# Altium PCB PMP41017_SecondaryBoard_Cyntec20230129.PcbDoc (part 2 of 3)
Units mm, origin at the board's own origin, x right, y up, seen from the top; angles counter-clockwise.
Board outline 56.93 x 50 mm, 6 copper layers (Top Layer, Layer 1, Layer 3, Layer 4, Layer 2, Bottom Layer), stack 1.219 mm thick; 147 components, 63 nets, 876 pads, 1174 vias.
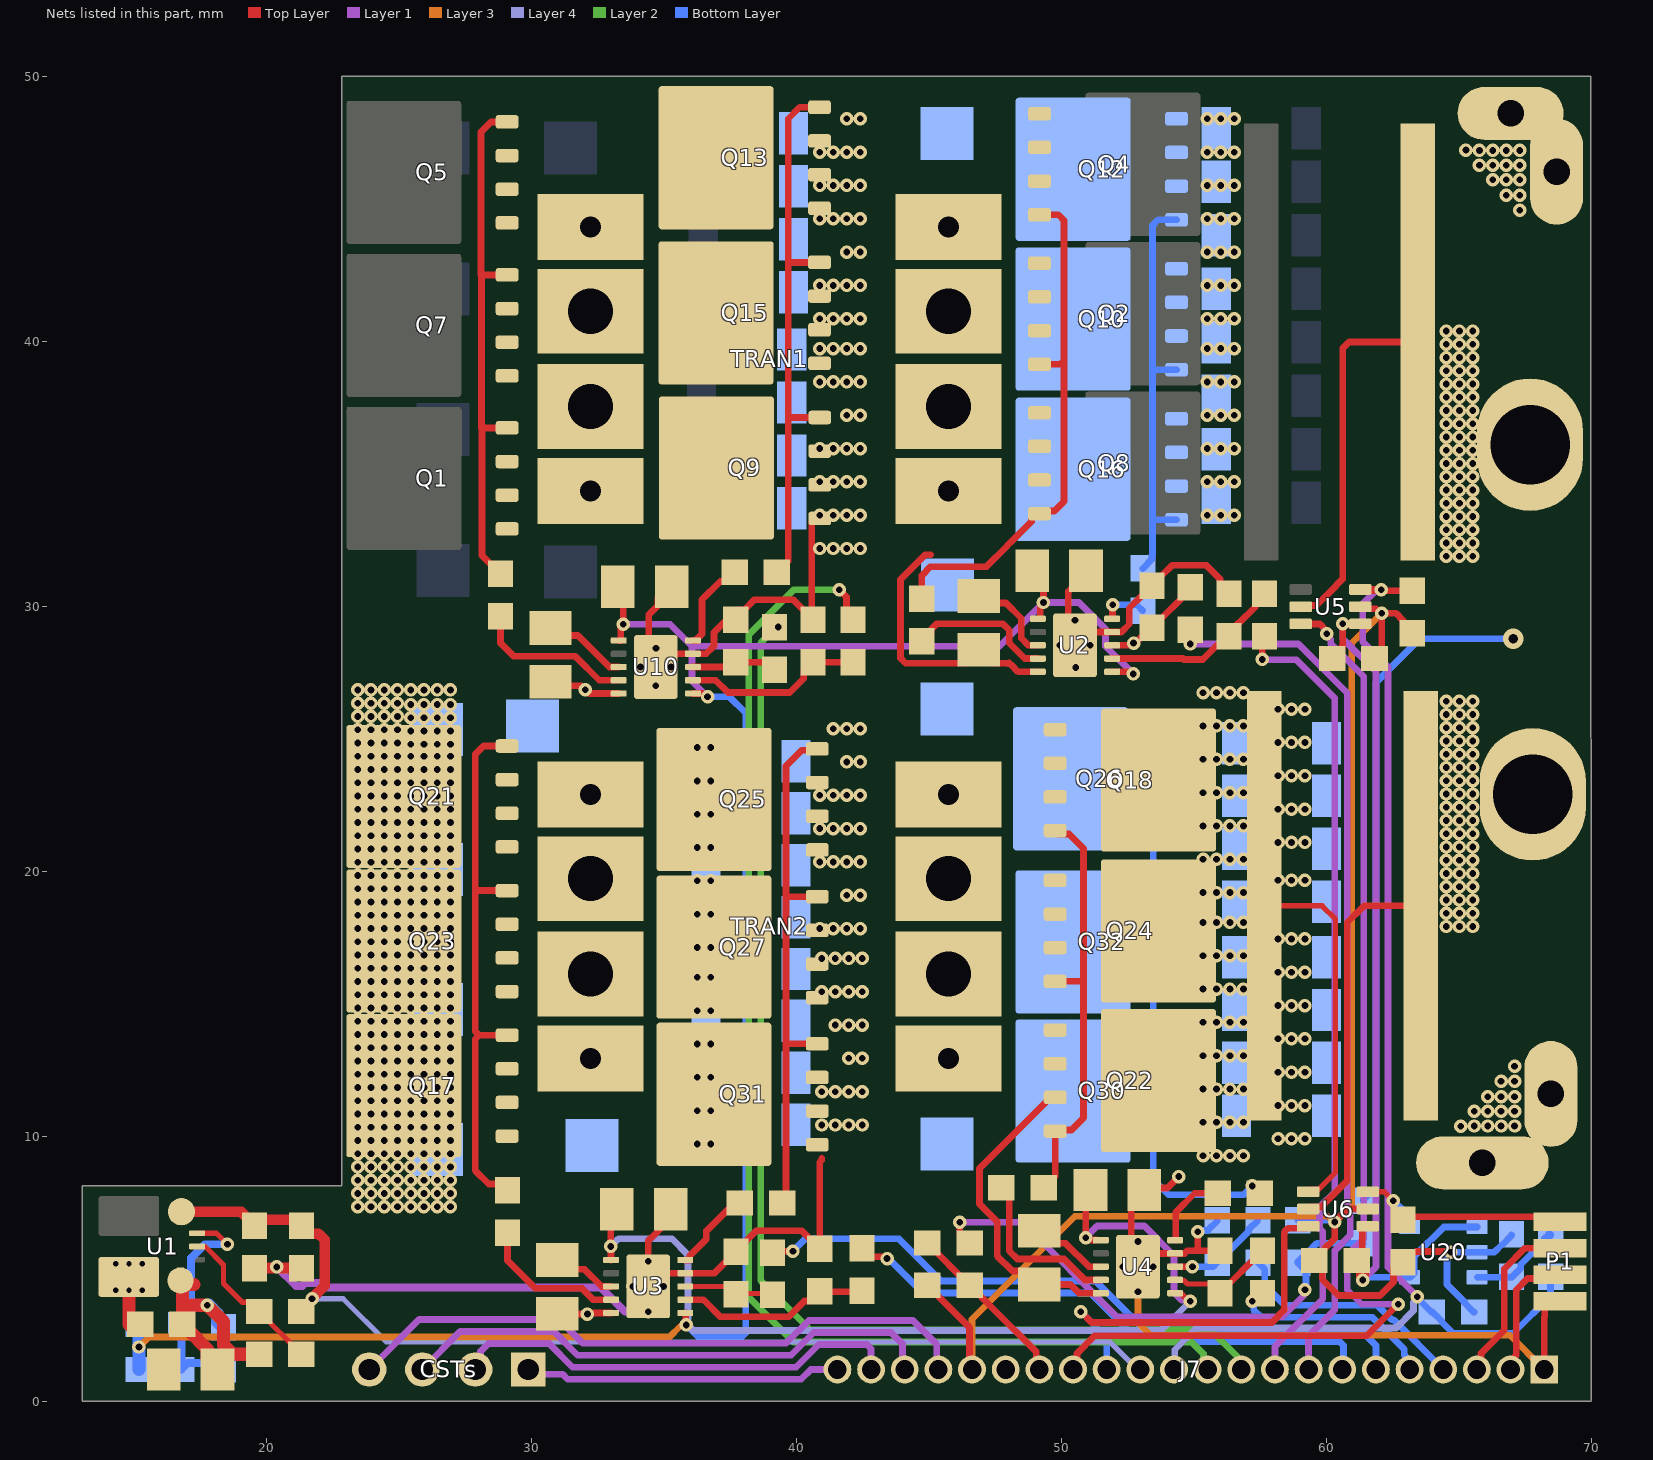
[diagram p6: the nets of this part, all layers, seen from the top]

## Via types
v1: diameter 0.508, hole 0.254, Top Layer to Bottom Layer, tented both sides, 996 vias
v2: diameter 0.508, hole 0.254, Layer 2 to Bottom Layer, tented both sides, 151 vias
v3: diameter 0.508, hole 0.254, Top Layer to Bottom Layer, 14 vias
v4: diameter 0.5, hole 0.2, Top Layer to Bottom Layer, 12 vias
v5: diameter 0.762, hole 0.356, Top Layer to Bottom Layer, tented both sides, 1 vias

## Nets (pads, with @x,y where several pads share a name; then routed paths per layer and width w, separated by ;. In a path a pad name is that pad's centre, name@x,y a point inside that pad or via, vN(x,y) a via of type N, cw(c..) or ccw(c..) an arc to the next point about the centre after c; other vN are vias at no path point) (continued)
12Vo_B: C25.1 C26.1 C27.1 C28.1 C29.1 C30.1 C31.1 C32.1 C33.1 C34.1 C35.1 C36.1 C37.1 C38.1 C39.1 C40.1 MP7.1 MP8.1 MP9.1 MP10.1 MP11.1 MP12.1 Q17.5 Q17.6 Q17.7 Q17.8 Q17.9@25.196,11.911 Q18.5 Q18.6 Q18.7 Q18.8 Q18.9@53.676,23.442 Q21.5 Q21.6 Q21.7 Q21.8 Q21.9@25.196,22.823 Q22.5 Q22.6 Q22.7 Q22.8 Q22.9@53.676,12.102 Q23.5 Q23.6 Q23.7 Q23.8 Q23.9@25.196,17.367 Q24.5 Q24.6 Q24.7 Q24.8 Q24.9@53.676,17.752 R56.2 R94.2 R97.2 R105.2 R117.2 U6.4 | length 13.6
  Top Layer w0.2: R117.2@57.675,18.696 59.854,18.696 60.356,18.194 60.356,8.635 59.727,8.005 U6.4@59.426,8.005
  other v1: 23.456,7.343 23.956,7.343 24.456,7.343 24.956,7.343 25.456,7.343 25.956,7.343 26.456,7.343 26.956,7.343 23.456,7.843 23.956,7.843 24.456,7.843 24.956,7.843 25.456,7.843 25.956,7.843 26.456,7.843 26.956,7.843 23.456,8.343 23.956,8.343 24.456,8.343 24.956,8.343 25.456,8.343 25.956,8.343 26.456,8.343 26.956,8.343 23.456,8.843 23.956,8.843 24.456,8.843 24.956,8.843 25.456,8.843 25.956,8.843 26.456,8.843 26.956,8.843 23.456,9.343 23.956,9.343 24.456,9.343 24.956,9.343 25.456,9.343 25.956,9.343 26.456,9.343 26.956,9.343 23.456,9.843 23.956,9.843 24.456,9.843 24.956,9.843 25.456,9.843 25.956,9.843 26.456,9.843 26.956,9.843 58.187,9.904 58.695,9.904 59.203,9.904 23.456,10.343 23.956,10.343 24.456,10.343 24.956,10.343 25.456,10.343 25.956,10.343 26.456,10.343 26.956,10.343 23.456,10.843 23.956,10.843 24.456,10.843 24.956,10.843 25.456,10.843 25.956,10.843 26.456,10.843 26.956,10.843 58.187,11.161 58.695,11.161 59.203,11.161 23.456,11.343 23.956,11.343 24.456,11.343 24.956,11.343 25.456,11.343 25.956,11.343 26.456,11.343 26.956,11.343 23.456,11.843 23.956,11.843 24.456,11.843 24.956,11.843 25.456,11.843 25.956,11.843 26.456,11.843 26.956,11.843 23.456,12.343 23.956,12.343 24.456,12.343 24.956,12.343 25.456,12.343 25.956,12.343 26.456,12.343 26.956,12.343 58.187,12.418 58.695,12.418 59.203,12.418 23.456,12.843 23.956,12.843 24.456,12.843 24.956,12.843 25.456,12.843 25.956,12.843 26.456,12.843 26.956,12.843 23.456,13.343 23.956,13.343 24.456,13.343 24.956,13.343 25.456,13.343 25.956,13.343 26.456,13.343 26.956,13.343 58.187,13.676 58.695,13.676 59.203,13.676 23.456,13.843 23.956,13.843 24.456,13.843 24.956,13.843 25.456,13.843 25.956,13.843 26.456,13.843 26.956,13.843 23.456,14.343 23.956,14.343 24.456,14.343 24.956,14.343 25.456,14.343 25.956,14.343 26.456,14.343 26.956,14.343 23.456,14.843 23.956,14.843 24.456,14.843 24.956,14.843 25.456,14.843 25.956,14.843 26.456,14.843 26.956,14.843 58.187,14.933 58.695,14.933 59.203,14.933 23.456,15.343 23.956,15.343 24.456,15.343 24.956,15.343 25.456,15.343 25.956,15.343 26.456,15.343 26.956,15.343 23.456,15.843 23.956,15.843 24.456,15.843 24.956,15.843 25.456,15.843 25.956,15.843 26.456,15.843 26.956,15.843 58.187,16.191 58.695,16.191 59.203,16.191 23.456,16.343 23.956,16.343 24.456,16.343 24.956,16.343 25.456,16.343 25.956,16.343 26.456,16.343 26.956,16.343 23.456,16.843 23.956,16.843 24.456,16.843 24.956,16.843 25.456,16.843 25.956,16.843 26.456,16.843 26.956,16.843 23.456,17.343 23.956,17.343 24.456,17.343 24.956,17.343 25.456,17.343 25.956,17.343 26.456,17.343 26.956,17.343 58.187,17.448 58.695,17.448 59.203,17.448 23.456,17.843 23.956,17.843 24.456,17.843 24.956,17.843 25.456,17.843 25.956,17.843 26.456,17.843 26.956,17.843 23.456,18.343 23.956,18.343 24.456,18.343 24.956,18.343 25.456,18.343 25.956,18.343 26.456,18.343 26.956,18.343 23.456,18.843 23.956,18.843 24.456,18.843 24.956,18.843 25.456,18.843 25.956,18.843 26.456,18.843 26.956,18.843 23.456,19.343 23.956,19.343 24.456,19.343 24.956,19.343 25.456,19.343 25.956,19.343 26.456,19.343 26.956,19.343 58.187,19.657 58.695,19.657 59.203,19.657 23.456,19.843 23.956,19.843 24.456,19.843 24.956,19.843 25.456,19.843 25.956,19.843 26.456,19.843 26.956,19.843 23.456,20.343 23.956,20.343 24.456,20.343 24.956,20.343 25.456,20.343 25.956,20.343 26.456,20.343 26.956,20.343 23.456,20.843 23.956,20.843 24.456,20.843 24.956,20.843 25.456,20.843 25.956,20.843 26.456,20.843 26.956,20.843 58.187,21.089 58.695,21.089 59.203,21.089 23.456,21.343 23.956,21.343 24.456,21.343 24.956,21.343 25.456,21.343 25.956,21.343 26.456,21.343 26.956,21.343 23.456,21.843 23.956,21.843 24.456,21.843 24.956,21.843 25.456,21.843 25.956,21.843 26.456,21.843 26.956,21.843 23.456,22.343 23.956,22.343 24.456,22.343 24.956,22.343 25.456,22.343 25.956,22.343 26.456,22.343 26.956,22.343 58.187,22.346 58.695,22.346 59.203,22.346 23.456,22.843 23.956,22.843 24.456,22.843 24.956,22.843 25.456,22.843 25.956,22.843 26.456,22.843 26.956,22.843 23.456,23.343 23.956,23.343 24.456,23.343 24.956,23.343 25.456,23.343 25.956,23.343 26.456,23.343 26.956,23.343 58.187,23.603 58.695,23.603 59.203,23.603 23.456,23.843 23.956,23.843 24.456,23.843 24.956,23.843 25.456,23.843 25.956,23.843 26.456,23.843 26.956,23.843 23.456,24.343 23.956,24.343 24.456,24.343 24.956,24.343 25.456,24.343 25.956,24.343 26.456,24.343 26.956,24.343 25.456,24.79 25.956,24.79 26.456,24.79 26.956,24.79 23.456,24.843 23.956,24.843 24.456,24.843 24.956,24.843 58.187,24.861 58.695,24.861 59.203,24.861 25.456,25.29 25.956,25.29 26.456,25.29 26.956,25.29 23.456,25.343 23.956,25.343 24.456,25.343 24.956,25.343 25.456,25.79 25.956,25.79 26.456,25.79 26.956,25.79 23.456,25.843 23.956,25.843 24.456,25.843 24.956,25.843 58.187,26.118 58.695,26.118 59.203,26.118 25.456,26.29 25.956,26.29 26.456,26.29 26.956,26.29 23.456,26.343 23.956,26.343 24.456,26.343 24.956,26.343 23.456,26.843 23.956,26.843 24.456,26.843 24.956,26.843 25.456,26.843 25.956,26.843 26.456,26.843 26.956,26.843
  other v2: 36.272,9.711 36.78,9.711 36.272,10.969 36.78,10.969 36.272,12.226 36.78,12.226 36.272,13.484 36.78,13.484 36.272,14.741 36.78,14.741 36.272,15.998 36.78,15.998 36.272,17.124 36.78,17.124 36.272,18.381 36.78,18.381 36.272,19.639 36.78,19.639 36.272,20.896 36.78,20.896 36.272,22.154 36.78,22.154 36.272,23.411 36.78,23.411 36.272,24.668 36.78,24.668
12Vout: pad.4@67.7,36.1 pad.5 R26.1 R29.1 R56.1 R89.1 R92.1 R94.1 R96.1 R97.1 R105.1 R108.1 R117.1 U5.5 U6.5 | length 54
  Top Layer w0.254: U5.5@59.043,29.984 59.084,30.025 59.629,30.025 60.128,30.524 60.128,30.527 60.627,31.026 60.627,39.727 60.873,39.973 R29.1@63.453,39.973 ; U6.5@59.399,7.328 59.804,7.328 59.854,7.378 59.858,7.378 60.078,7.599 60.078,7.602 60.796,8.32 60.796,18.057 61.436,18.696 R117.1@63.575,18.696
  Bottom Layer w0.254: R96.1@61.403,7.567 61.403,7.592 61.88,8.07 61.88,27.129 63.523,28.771 v5(67.061,28.771) ; pad.5@67.8,22.777 pad.5@67.8,22.9
  other v1: 64.532,17.916 65.032,17.916 65.532,17.916 64.532,18.416 65.032,18.416 65.532,18.416 64.532,18.916 65.032,18.916 65.532,18.916 64.532,19.416 65.032,19.416 65.532,19.416 64.532,19.916 65.032,19.916 65.532,19.916 64.532,20.416 65.032,20.416 65.532,20.416 64.532,20.916 65.032,20.916 65.532,20.916 64.532,21.416 65.032,21.416 65.532,21.416 64.532,21.916 65.032,21.916 65.532,21.916 64.532,22.416 65.032,22.416 65.532,22.416 64.532,22.916 65.032,22.916 65.532,22.916 64.532,23.416 65.032,23.416 65.532,23.416 64.532,23.916 65.032,23.916 65.532,23.916 64.532,24.416 65.032,24.416 65.532,24.416 64.532,24.916 65.032,24.916 65.532,24.916 64.532,25.416 65.032,25.416 65.532,25.416 64.532,25.916 65.032,25.916 65.532,25.916 64.532,26.416 65.032,26.416 65.532,26.416 64.532,31.886 65.032,31.886 65.532,31.886 64.532,32.386 65.032,32.386 65.532,32.386 64.532,32.886 65.032,32.886 65.532,32.886 64.532,33.386 65.032,33.386 65.532,33.386 64.532,33.886 65.032,33.886 65.532,33.886 64.532,34.386 65.032,34.386 65.532,34.386 64.532,34.886 65.032,34.886 65.532,34.886 64.532,35.386 65.032,35.386 65.532,35.386 64.532,35.886 65.032,35.886 65.532,35.886 64.532,36.386 65.032,36.386 65.532,36.386 64.532,36.886 65.032,36.886 65.532,36.886 64.532,37.386 65.032,37.386 65.532,37.386 64.532,37.886 65.032,37.886 65.532,37.886 64.532,38.386 65.032,38.386 65.532,38.386 64.532,38.886 65.032,38.886 65.532,38.886 64.532,39.386 65.032,39.386 65.532,39.386 64.532,39.886 65.032,39.886 65.532,39.886 64.532,40.386 65.032,40.386 65.532,40.386
12Vs: C5.1 C6.1 J7.13 R1.1 U1.1 | length 42.6
  Top Layer w0.2: C5.1@19.183,6.228 19.558,6.603 C5.1@19.558,6.628 ; C5.1@19.454,6.757 19.583,6.628 C5.1@19.59,6.635 ; R1.1@21.336,3.384 21.736,3.784 v1(21.736,3.868) ; C6.1@21.336,6.603 21.431,6.508 21.711,6.228 C6.1@21.736,6.228
  Top Layer w0.4: U1.1@16.806,7.154 19.057,7.154 C5.1@19.454,6.757 ; C5.1@19.59,6.635 19.81,6.856 21.109,6.856 C6.1@21.336,6.628 21.336,6.603 21.611,6.328 21.977,6.328 22.211,6.094 22.211,4.362 21.736,3.887 v1(21.736,3.868)
  Layer 4 w0.2: v1(21.736,3.868) 22.911,3.868 24.538,2.24 51.847,2.24 52.887,1.2 J7.13@52.99,1.2
LV_SW1A: C19.2 Q1.1 Q1.2 Q1.3 Q5.1 Q5.2 Q5.3 Q7.1 Q7.2 Q7.3 Q9.5 Q9.6 Q9.7 Q9.8 Q9.9@36.993,35.219 Q13.5 Q13.6 Q13.7 Q13.8 Q13.9@36.983,46.925 Q15.5 Q15.6 Q15.7 Q15.8 Q15.9@36.983,41.072 TRAN1.1 TRAN1.1ab TRAN1.1cd TRAN1.1e U10.5 | length 2.8
  Top Layer w0.254: C19.2@30.712,26.911 C19.2@30.76,26.959 ; C19.2@30.734,27.15 30.884,27 31.895,27 32.186,26.709 U10.5@33.306,26.709
  other v1: 32.041,26.854
LV_SW1B: C20.2 MP13.1 MP15.1 Q2.1 Q2.2 Q2.3 Q4.1 Q4.2 Q4.3 Q8.1 Q8.2 Q8.3 Q10.5 Q10.6 Q10.7 Q10.8 Q10.9@50.455,40.834 Q12.5 Q12.6 Q12.7 Q12.8 Q12.9@50.456,46.49 Q16.5 Q16.6 Q16.7 Q16.8 Q16.9@50.455,35.171 TRAN1.2 TRAN1.2ab TRAN1.2cd TRAN1.2e U2.5 | length 10.3
  Top Layer w0.254: 45.072,31.948 44.884,31.948 43.943,31.007 43.943,28.041 44.135,27.85 46.383,27.85 C20.2@46.889,28.355 47.397,27.847 47.988,27.847 48.008,27.827 ; 48.044,27.862 48.044,27.86 48.126,27.778 48.128,27.778 48.379,27.527 U2.5@49.125,27.527
LV_SW2A: C43.2 Q17.1 Q17.2 Q17.3 Q21.1 Q21.2 Q21.3 Q23.1 Q23.2 Q23.3 Q25.5 Q25.6 Q25.7 Q25.8 Q25.9@36.901,22.712 Q27.5 Q27.6 Q27.7 Q27.8 Q27.9@36.901,17.136 Q31.5 Q31.6 Q31.7 Q31.8 Q31.9@36.901,11.586 TRAN2.1 TRAN2.1ab TRAN2.1cd TRAN2.1e U3.5 | length 2
  Top Layer w0.25: C43.2@30.988,3.302 30.997,3.293 v1(32.128,3.293) ; v1@32.131,3.302 32.163,3.334 U3.5@33.02,3.334
LV_SW2B: C44.2 MP14.1 MP16.1 Q18.1 Q18.2 Q18.3 Q22.1 Q22.2 Q22.3 Q24.1 Q24.2 Q24.3 Q26.5 Q26.6 Q26.7 Q26.8 Q26.9@50.36,23.491 Q30.5 Q30.6 Q30.7 Q30.8 Q30.9@50.455,11.712 Q32.5 Q32.6 Q32.7 Q32.8 Q32.9@50.455,17.335 TRAN2.2 TRAN2.2ab TRAN2.2cd TRAN2.2e U4.5 | length 12
  Top Layer w0.254: Q22.3@49.776,11.467 49.601,11.467 46.92,8.786 46.92,7.448 47.59,6.778 47.59,5.49 48.165,4.915 48.672,4.915 C44.2@49.18,4.407 50.352,4.407 50.679,4.08 U4.5@51.502,4.08
NetC19_1: C19.1 U10.3 | length 2.8
  Top Layer w0.254: C19.1@31.021,28.896 31.766,28.896 32.953,27.709 U10.3@33.306,27.709
NetC20_1: C20.1 U2.3 | length 3.4
  Top Layer w0.254: C20.1@46.889,30.387 47.151,30.125 47.921,30.125 48.498,29.548 48.498,28.801 48.772,28.527 U2.3@49.125,28.527
NetC21_2: C21.2 R47.2 U10.8 | length 3.1
  Top Layer w0.254: U10.8@36.106,27.709 C21.2@37.722,27.709 ; C21.2@37.722,27.89 R47.2@39.186,27.89
NetC22_2: C22.2 R42.2 U10.7 | length 6.9
  Top Layer w0.254: U10.7@36.106,27.209 36.966,27.209 37.428,26.747 39.761,26.747 39.988,26.974 40.291,27.277 40.291,27.542 C22.2@40.639,27.89 R42.2@42.15,27.89
NetC23_2: C23.2 R49.2 U2.8 | length 4
  Top Layer w0.254: U2.8@51.925,28.527 52.584,28.527 52.67,28.613 v1(52.737,28.613) 52.803,28.613 53,28.809 53.08,28.809 53.428,29.157 C23.2@53.428,29.182 53.428,29.207 53.776,29.555 53.801,29.555 54.526,30.281 54.526,30.371 R49.2@54.874,30.719 ; R49.2@54.521,30.974 R49.2@54.546,30.974
NetC24_2: C24.2 R44.2 U2.7 | length 6.9
  Top Layer w0.254: U2.7@51.925,28.027 54.602,28.027 54.634,27.996 55.347,27.996 55.969,28.617 55.994,28.617 56.342,28.965 56.342,28.99 56.342,29.015 56.69,29.363 56.715,29.363 57.327,29.976 57.327,30.122 R44.2@57.675,30.47
NetC43_1: C43.1 U3.3 | length 2.8
  Top Layer w0.254: C43.1@31.234,5.58 C43.1@30.988,5.334 31.341,4.981 32.02,4.981 32.667,4.334 U3.3@33.02,4.334
NetC44_1: C44.1 U4.3 | length 2.9
  Top Layer w0.254: C44.1@49.18,6.439 49.659,5.96 50.167,5.96 51.047,5.08 U4.3@51.502,5.08
NetC45_2: C45.2 R87.2 U3.8 | length 3.7
  Top Layer w0.2: U3.8@35.82,4.334 37.437,4.334 C45.2@37.728,4.042 C45.2@37.566,3.88 ; C45.2@37.728,4.065 39.059,4.065 R87.2@39.112,4.012
NetC46_2: C46.2 R67.2 U3.7 | length 7.3
  Top Layer w0.254: U3.7@35.82,3.834 36.499,3.834 37.148,3.185 39.722,3.185 40.32,3.783 40.546,3.783 40.894,4.131 R67.2@42.412,4.131
NetC47_2: C47.2 R88.2 U4.8 | length 3.9
  Top Layer w0.254: U4.8@54.302,5.08 v1(54.957,5.08)
  Bottom Layer w0.254: v1(54.957,5.08) 55.745,5.08 C47.2@55.895,5.23 55.895,5.255 56.243,5.603 56.268,5.603 57.079,6.413 57.079,6.482 R88.2@57.427,6.83
NetC48_2: C48.2 R86.2 U4.7 | length 3.6
  Top Layer w0.2: U4.7@54.302,4.58 54.322,4.56 54.637,4.56 54.772,4.425 55.676,4.425 55.994,4.107 C48.2@55.994,4.082
  Top Layer w0.254: C48.2@55.994,4.107 56.342,4.455 56.367,4.455 R86.2@57.18,5.268
NetC51_2: C51.2 R3.1 R5.2 U1.7 | length 9.6
  Top Layer w0.2: U1.7@17.394,6.342 18.126,6.342 v1(18.542,5.926)
  Bottom Layer w0.2: R5.2@18.392,1.2 18.392,1.225 18.767,1.6 R5.2@18.792,1.6 ; v1@18.542,5.893 v1(18.542,5.926)
  Bottom Layer w0.3: R5.2@18.392,1.451 17.053,1.451 C51.2@16.802,1.2 R3.1@16.802,2.899 16.827,2.899 17.152,3.224 17.152,3.376 17.176,3.4 17.176,5.408 17.694,5.926 v1(18.542,5.926)
NetQ1_4: Q1.4 Q5.4 Q7.4 R31.2 | length 20.1
  Top Layer w0.254: 28.131,42.505 28.131,36.731 Q1.4@29.096,36.731 ; 28.149,36.731 28.149,31.915 28.472,31.592 28.497,31.592 28.845,31.244 R31.2@28.845,31.219 ; Q7.4@29.096,42.505 28.114,42.505 28.114,47.897 28.496,48.278 Q5.4@29.096,48.278
NetQ2_4: Q2.4 Q4.4 Q8.4 R34.2 | length 20.1
  Top Layer w0.254: R34.2@44.745,30.277 44.745,31.167 45.072,31.494 47.184,31.494 47.95,32.259 47.95,32.27 48.141,32.461 48.151,32.461 48.883,33.193 48.883,33.368 49.011,33.496 Q8.4@49.186,33.496 49.285,33.594 49.745,33.594 50.111,33.96 50.111,39.261 ; Q2.4@49.186,39.135 49.985,39.135 50.111,39.261 ; Q4.4@49.186,44.775 49.897,44.775 50.111,44.562 50.111,39.261
NetQ9_4: Q9.4 Q13.4 Q15.4 R36.2 | length 21.4
  Top Layer w0.254: R36.2@38.903,31.104 38.928,31.104 R36.2@39.196,31.371 ; R36.2@39.28,31.287 39.305,31.287 39.653,31.635 39.653,31.66 39.704,31.712 39.704,37.124 ; Q15.4@40.883,42.977 39.704,42.977 ; Q13.4@40.883,48.83 40.137,48.83 39.704,48.396 39.704,42.977 ; Q9.4@40.893,37.124 39.704,37.124 ; 39.704,37.124 39.704,42.977
NetQ10_4: Q10.4 Q12.4 Q16.4 R39.2 | length 16
  Bottom Layer w0.254: R39.2@53.086,31.429 53.434,31.777 53.434,31.938 53.446,31.95 53.446,33.266 ; Q16.4@54.355,33.266 53.446,33.266 ; Q10.4@54.355,38.929 53.558,38.929 53.446,38.817 ; Q12.4@54.356,44.585 53.663,44.585 53.446,44.369 53.446,38.817 ; 53.446,33.266 53.446,38.817
NetQ17_4: Q17.4 Q21.4 Q23.4 R58.2 | length 20.9
  Top Layer w0.254: Q17.4@29.096,13.816 28.045,13.816 ; Q23.4@29.096,19.272 27.89,19.272 ; Q21.4@29.096,24.728 28.211,24.728 27.89,24.406 27.89,19.272 ; R58.2@29.111,7.968 28.88,8.2 28.404,8.2 27.89,8.714 27.89,13.661 28.045,13.816 ; 27.89,19.272 27.89,13.972 28.045,13.816
NetQ18_4: Q18.4 Q22.4 Q24.4 R59.2 | length 16.2
  Top Layer w0.254: R59.2@49.347,8.059 49.372,8.059 49.72,8.407 49.72,8.432 49.776,8.488 Q22.4@49.776,10.197 49.818,10.239 50.392,10.239 50.85,10.697 50.85,15.847 ; Q24.4@49.776,15.847 50.85,15.847 ; Q18.4@49.776,21.537 49.904,21.409 50.304,21.409 50.85,20.863 50.85,15.847
NetQ25_4: Q25.4 Q27.4 Q31.4 R62.2 | length 20.3
  Top Layer w0.254: R62.2@39.483,7.484 39.624,7.625 39.624,13.474 ; 39.658,19.041 Q27.4@40.801,19.041 ; Q31.4@40.801,13.491 39.641,13.491 39.624,13.474 ; Q25.4@40.801,24.617 40.756,24.572 40.225,24.572 39.624,23.972 39.624,13.474
NetQ26_4: Q26.4 Q30.4 Q32.4 R63.2 | length 20.4
  Top Layer w0.254: v1(57.218,8.127) 57.494,7.851 R63.2@57.503,7.851
  Bottom Layer w0.254: 53.477,9.807 Q30.4@54.355,9.807 ; Q26.4@53.998,21.458 Q26.4@54.126,21.586 ; Q26.4@54.26,21.586 Q26.4@54.126,21.586 ; Q32.4@54.355,15.43 53.477,15.43 ; v1(57.218,8.127) 56.882,7.791 54.062,7.791 53.477,8.376 53.477,15.43 ; 53.477,15.43 53.477,20.67 53.477,21.425 53.637,21.586 Q26.4@54.126,21.586
NetR1_2: R1.2 R2.1 U1.6 | length 6
  Top Layer w0.2: U1.6@17.394,5.842 17.404,5.832 17.709,5.832 18.392,5.149 18.392,4.441 19.093,3.74 19.38,3.74 R1.2@19.736,3.384 ; R1.2@19.761,3.384 20.136,3.009 20.136,2.984 20.936,2.184 20.936,2.153 21.311,1.778 R2.1@21.336,1.778
NetR23_2: R23.2 R96.2 R98.1 | length 19.9
  Top Layer w0.254: v1(46.174,6.758) 46.174,6.323 46.522,5.975 R98.1@46.547,5.975
  Layer 1 w0.254: v1(46.174,6.758) 48.534,6.758 52.099,3.194 58.365,3.194 59.154,3.983 59.154,4.161 v1(59.203,4.21)
  Bottom Layer w0.254: v1(59.203,4.21) 59.247,4.254 59.247,4.911 R23.2@58.928,5.23 58.928,5.255 59.276,5.603 59.301,5.603 59.665,5.967 R96.2@61.403,5.967
NetR118_1: R118.1 R119.2 U20.3 | length 3.9
  Bottom Layer w0.254: U20.3@65.7,4.679 67.001,4.679 67.349,5.027 67.349,5.171 68.108,5.93 68.133,5.93 R118.1@68.228,6.025 ; R118.1@68.402,6.328 68.402,6.303 68.228,6.129 R118.1@68.228,6.025 ; R118.1@68.481,6.303 68.481,6.278 R118.1@68.228,6.025
PB_3V3-s: C49.1 C50.1 C60.2 J7.12 P1.1 R118.2 U5.3 U6.3 U20.5 | length 56.9
  Top Layer w0.2: U6.3@61.576,7.905 62.202,7.905 v1(62.54,7.567) 62.54,7.218 C50.1@62.803,6.955
  Top Layer w0.254: v1(62.083,30.629) 62.08,30.631 61.688,30.631 61.729,30.59 C49.1@63.255,30.59 ; C50.1@62.894,6.965 68.649,6.965 P1.1@68.834,6.78
  Layer 1 w0.254: v1(62.083,30.629) 62.034,30.58 61.872,30.58 61.379,30.087 61.379,28.673 62.334,27.718 62.334,5.057 v1(63.441,3.95)
  Layer 4 w0.254: J7.12@54.26,1.2 54.289,1.229 54.289,1.945 55.114,2.77 62.649,2.77 63.3,3.421 63.3,3.74 63.441,3.881 v1(63.441,3.95)
  Bottom Layer w0.254: v1(62.54,7.567) 62.548,7.567 63.029,7.086 63.029,6.7 U20.5@63.15,6.579 ; v1(63.441,3.95) 63.441,3.898 63.968,3.371 C60.2@63.993,3.371 64.018,3.371 64.366,3.023 64.366,2.998 64.795,2.569 67.064,2.569 68.466,3.97 68.466,4.688 R118.2@68.481,4.703
PB_AGND-s: C49.2 C50.2 C54.2 C55.1 C56.1 C60.1 J7.18 R23.1 R119.1 U5.2 U6.2 U20.2 | length 66
  Top Layer w0.254: C54.2@44.947,4.379 44.972,4.379 45.32,4.031 45.32,4.006 46.547,2.779 46.547,1.293 J7.18@46.64,1.2 ; C56.1@59.556,5.307 59.856,5.007 59.856,4.601 60.465,3.992 62.039,3.992 62.544,4.498 62.544,5.016 C50.2@62.758,5.23 ; C56.1@59.57,5.319 59.57,5.356 59.556,5.369 59.581,5.369 59.929,5.717 59.929,5.742 60.332,6.145 v1(60.332,6.765) 60.332,6.791 60.796,7.255 U6.2@61.576,7.255 ; U5.2@61.293,29.984 61.366,29.911 61.862,29.911 62.035,29.739 v1(62.103,29.739) ; C55.1@61.827,28.025 62.103,28.301 v1(62.103,29.739) ; C50.2@62.907,5.275 63.255,5.623 63.378,5.623 63.404,5.649 64.684,5.649 v1(64.71,5.623) ; C49.2@63.255,28.99 62.907,29.338 62.907,29.464 62.633,29.739 v1(62.103,29.739)
  Layer 3 w0.254: J7.18@46.64,1.2 46.64,3.097 50.525,6.982 60.057,6.982 60.273,6.765 v1(60.332,6.765) 60.972,7.405 60.972,28.623 61.121,28.771 61.136,28.771 v1(62.103,29.739)
  Bottom Layer w0.254: R23.1@58.928,6.83 60.199,6.83 60.264,6.765 v1(60.332,6.765) ; C60.1@65.593,3.371 65.568,3.371 65.22,3.719 65.22,3.744 64.561,4.403 64.561,5.603 64.587,5.629 U20.2@65.7,5.629 66.351,5.629 66.628,5.906 66.653,5.906 67.001,6.254 R119.1@67.001,6.279
PB_CT1+: CSTs.1 J7.22 | length 12
  Layer 1 w0.254: CSTs.1@29.894,1.2 30.078,1.016 31.198,1.016 31.383,0.831 40.19,0.831 40.559,1.2 J7.22@41.56,1.2
PB_CT1-: CSTs.2 J7.21 | length 17.2
  Layer 1 w0.254: CSTs.2@27.894,1.2 28.094,1.4 28.094,1.883 28.387,2.177 30.679,2.177 31.571,1.285 40.002,1.285 40.857,2.14 42.674,2.14 42.83,1.984 J7.21@42.83,1.2
PB_CT2+: CSTs.3 J7.20 | length 20.6
  Layer 1 w0.254: CSTs.3@25.894,1.2 27.325,2.631 30.867,2.631 31.759,1.739 39.814,1.739 40.669,2.594 43.585,2.594 44.015,2.164 44.015,1.285 J7.20@44.1,1.2
PB_CT2-: CSTs.4 J7.19 | length 24.3
  Layer 1 w0.254: CSTs.4@23.894,1.2 25.779,3.085 31.055,3.085 31.947,2.193 39.626,2.193 40.481,3.048 44.412,3.048 45.305,2.155 45.305,1.265 J7.19@45.37,1.2
PB_ISEC1: J7.15 U5.6 | length 42.5
  Top Layer w0.254: J7.15@50.45,1.2 50.603,1.352 50.603,1.808 51.272,2.477 61.535,2.477 v1(62.719,3.661) ; U5.6@59.043,29.334 59.045,29.332 59.764,29.332 59.981,29.115 59.981,29.014 v1(60.03,28.965)
  Layer 1 w0.254: v1(60.03,28.965) 60.03,28.897 60.173,28.753 60.173,28.595 61.426,27.342 61.426,6.146 60.798,5.518 60.798,4.208 61.345,3.661 v1(62.719,3.661)
PB_ISEC2: J7.14 U6.6 | length 14.6
  Top Layer w0.254: v1(50.742,3.384) 51.154,2.972 57.954,2.972 58.42,3.438 58.42,6.383 58.569,6.532 59.253,6.532 U6.6@59.326,6.605
  Bottom Layer w0.254: v1(50.742,3.384) 51.72,2.405 J7.14@51.72,1.2
PB_URAT2_RX: J7.3 P1.2 | length 6.7
  Top Layer w0.254: J7.3@65.69,1.2 65.843,1.352 65.843,1.803 66.727,2.688 66.727,5.003 67.504,5.78 P1.2@68.834,5.78
PB_URAT2_TX: J7.2 P1.3 | length 5
  Top Layer w0.254: J7.2@66.96,1.2 67.113,1.352 67.113,1.678 67.181,1.747 67.181,4.21 67.602,4.631 68.685,4.631 P1.3@68.834,4.78
PB_VPRI: J7.17
PB_VSEC: C54.1 J7.16 R98.2 | length 6.6
  Top Layer w0.254: R98.2@44.947,5.975 44.972,5.975 45.32,5.627 45.32,5.606 46.174,4.752 46.174,4.727 46.522,4.379 C54.1@46.547,4.379 46.572,4.379 46.92,4.031 46.92,4.006 47.556,3.371 49.067,1.86 49.067,1.313 J7.16@49.18,1.2
SR1_AH: J7.11 R42.1 | length 49.2
  Top Layer w0.254: v1(41.631,30.629) 41.631,30.625 41.903,30.353 41.903,29.737 R42.1@42.15,29.49
  Layer 1 w0.254: J7.11@55.521,1.21 J7.11@55.53,1.2
  Layer 2 w0.254: v1(41.631,30.629) 39.92,30.629 38.21,28.919 38.21,3.932 39.901,2.24 54.927,2.24 55.378,1.789 55.378,1.352 J7.11@55.53,1.2
SR1_AL: J7.10 R47.1 | length 45.1
  Top Layer w0.254: R47.1@39.186,29.21 39.186,29.235 39.318,29.235 v1(39.333,29.22)
  Layer 1 w0.254: J7.10@56.8,1.2 J7.10@56.8,1.415
  Layer 2 w0.254: v1(39.333,29.22) 39.277,29.22 38.664,28.607 38.664,4.565 40.535,2.694 55.645,2.694 56.648,1.691 56.648,1.352 J7.10@56.8,1.2
SR1_BH: J7.9 R44.1 | length 30.6
  Top Layer w0.254: v1(57.596,27.996) 57.596,28.791 R44.1@57.675,28.87
  Layer 1 w0.254: v1(57.596,27.996) 57.605,27.987 58.867,27.987 60.332,26.522 60.332,7.908 59.751,7.327 59.751,6.525 59.878,6.398 59.878,3.87 58.07,2.062 J7.9@58.07,1.2
SR1_BL: J7.8 R49.1 | length 33.5
  Top Layer w0.254: v1(54.874,28.577) R49.1@54.874,29.119
  Layer 1 w0.254: v1(54.874,28.577) 58.952,28.577 60.798,26.731 60.798,7.121 60.913,7.006 60.913,6.275 60.332,5.694 60.332,3.459 59.34,2.467 J7.8@59.34,1.2
SR2_AH: J7.7 R67.1 | length 20.6
  Top Layer w0.254: R67.1@42.493,5.774 42.808,5.458 43.294,5.458 43.365,5.386 v1(43.434,5.386)
  Bottom Layer w0.254: v1(43.434,5.386) 43.494,5.386 44.792,4.089 51.11,4.089 52.948,2.251 60.51,2.251 60.658,2.102 60.658,1.248 J7.7@60.61,1.2
SR2_AL: J7.6 R87.1 | length 25.6
  Top Layer w0.254: R87.1@39.112,5.587 39.189,5.665 v1(39.881,5.665)
  Bottom Layer w0.254: v1(39.881,5.665) 40.345,6.129 43.887,6.129 45.473,4.543 51.298,4.543 53.136,2.705 61.278,2.705 61.88,2.102 J7.6@61.88,1.2
SR2_BH: J7.5 R86.1 | length 7.6
  Top Layer w0.254: R86.1@57.504,3.99 R86.1@57.596,4.082
  Bottom Layer w0.254: v1(57.218,3.775) 57.267,3.726 57.267,3.45 57.541,3.175 61.738,3.175 62.954,1.959 62.954,1.747 62.998,1.703 62.998,1.352 J7.5@63.15,1.2
SR2_BL: J7.4 R88.1 | length 9
  Bottom Layer w0.254: R88.1@57.427,5.23 57.689,4.968 57.689,4.374 58.434,3.629 61.926,3.629 62.475,3.08 62.54,3.08 J7.4@64.42,1.2
V0-out: C1.2 C2.2 C4.2 C5.2 C6.2 C7.2 C8.2 C9.2 C10.2 C11.2 C12.2 C13.2 C14.2 C15.2 C16.2 C17.2 C18.2 C21.1 C22.1 C23.1 C24.1 C25.2 C26.2 C27.2 C28.2 C29.2 C30.2 C31.2 C32.2 C33.2 C34.2 C35.2 C36.2 C37.2 C38.2 C39.2 C40.2 C41.2 C42.2 C45.1 C46.1 C47.1 C48.1 C101.2 C102.2 C103.2 C106.2 C137.2 J7.1 P1.4 pad.4@65.9,9 pad.4@66.963,48.6 pad.4@68.7,46.4 pad.4@68.481,11.6 Q9.1 Q9.2 Q9.3 Q10.1 Q10.2 Q10.3 Q12.1 Q12.2 Q12.3 Q13.1 Q13.2 Q13.3 Q15.1 Q15.2 Q15.3 Q16.1 Q16.2 Q16.3 Q25.1 Q25.2 Q25.3 Q26.1 Q26.2 Q26.3 Q27.1 Q27.2 Q27.3 Q30.1 Q30.2 Q30.3 Q31.1 Q31.2 Q31.3 Q32.1 Q32.2 Q32.3 R2.2 R5.1 U1.4 U2.9 U2.11 U3.9 U3.11 U4.9 U4.11 U10.9 U10.11 | length 98.4
  Top Layer w0.254: U3.11@34.254,3.88 34.504,4.13 U3.11@34.504,4.334 ; v1(34.706,27) U10.11@34.706,27.709 ; C41.2@35.281,7.072 35.281,6.907 34.773,6.399 34.42,6.046 v3(34.42,5.284) U3.11@34.42,4.334 34.92,4.834 U3.9@35.82,4.834 36.92,4.834 37.355,5.269 37.38,5.269 37.728,5.617 C45.1@37.728,5.642 37.728,5.667 38.076,6.015 38.501,6.439 40.211,6.439 40.521,6.129 40.546,6.129 C46.1@40.894,5.781 ; C17.2@35.281,30.516 34.975,30.516 34.793,30.334 34.793,30.028 34.773,30.008 34.437,29.672 34.437,27.978 U10.11@34.706,27.709 ; C46.1@40.894,5.756 C46.1@40.894,5.781 ; Q9.1@40.893,33.314 40.718,33.314 40.59,33.186 40.59,29.54 C22.1@40.639,29.49 39.881,30.248 38.431,30.248 38.07,29.888 38.07,29.863 37.797,29.863 37.374,29.441 37.338,29.441 36.902,29.005 36.902,28.507 36.604,28.209 U10.9@36.106,28.209 35.206,28.209 U10.11@34.706,27.709 ; 40.969,9.168 40.969,9.1 40.894,9.025 C46.1@40.894,5.781 ; U2.11@50.525,28.527 51.025,29.027 U2.9@51.925,29.027 52.278,29.027 52.574,29.323 52.574,29.929 53.055,30.409 53.08,30.409 53.428,30.757 C23.1@53.428,30.782 53.428,30.807 53.776,31.155 53.801,31.155 54.191,31.546 55.485,31.546 55.994,31.037 55.994,30.938 C24.1@56.342,30.59 ; v3(50.525,29.477) 50.398,29.477 50.275,29.6 50.275,30.557 50.379,30.661 50.436,30.661 50.944,31.169 C18.2@50.944,31.334 ; v1(54.443,8.481) 54.01,8.049 53.217,8.049 C42.2@53.143,7.975 52.652,7.484 52.652,5.33 U4.11@52.902,5.08 53.402,5.58 U4.9@54.302,5.58 54.655,5.58 54.757,5.682 55.067,5.682 ; v1(55.153,6.401) 55.153,5.768 55.067,5.682 ; C48.1@55.994,5.682 55.067,5.682 ; J7.1@68.23,1.2 68.23,3.176 68.252,3.198 68.252,3.557 68.475,3.78 P1.4@68.834,3.78
  Top Layer w0.4: C5.2@19.558,5.028 C6.2@21.336,5.028
  Top Layer w0.5: U1.4@16.77,4.561 U1.4@16.848,4.482 ; 17.268,4.41 16.921,4.41 U1.4@16.848,4.482 ; C2.2@18.554,1.75 18.169,1.365 C2.2@18.169,1.2 17.784,1.585 17.784,1.967 17.096,2.656 17.096,2.681 16.871,2.906 C1.2@16.846,2.906 16.846,3.628 16.848,3.626 ; R2.2@19.736,1.778 18.744,1.778 18.392,2.13 18.392,3.014 v1(17.78,3.626) 16.848,3.626 ; 16.848,3.626 U1.4@16.848,4.482
  Layer 1 w0.3: v1(20.407,5.072) 21.122,4.356 21.371,4.356 21.486,4.471 21.986,4.471 22.156,4.301 32.622,4.301 33.54,3.384 v3(34.42,3.384)
  Layer 3 w0.254: v3(52.902,4.13) 52.902,2.971 53.381,2.492 66.938,2.492 J7.1@68.23,1.2
  Layer 4 w0.254: J7.1@67.832,1.598 J7.1@68.23,1.2
  Bottom Layer w0.254: v1(55.153,6.401) 55.201,6.449 55.537,6.449 55.545,6.457 55.547,6.457 55.895,6.805 C47.1@55.895,6.83
  Bottom Layer w0.5: v1(17.78,3.626) 17.782,3.625 17.836,3.625 18.167,3.294 18.167,3.025 R5.1@18.392,2.8 ; v1@20.405,5.072 v1(20.407,5.072)
  other v1: 65.081,10.377 65.589,10.388 66.097,10.388 66.605,10.388 67.113,10.388 40.969,10.426 41.477,10.426 41.985,10.426 42.493,10.426 65.589,10.945 66.097,10.946 66.605,10.946 67.113,10.946 66.097,11.494 66.605,11.494 67.113,11.494 40.969,11.683 41.477,11.683 41.985,11.683 42.493,11.683 66.605,12.08 67.113,12.08 67.113,12.643 41.985,12.941 42.493,12.941 41.477,14.198 41.985,14.198 42.493,14.198 40.969,15.456 41.477,15.456 41.985,15.456 42.493,15.456 40.969,16.713 41.477,16.713 41.985,16.713 42.493,16.713 40.894,17.839 41.402,17.839 41.91,17.839 42.418,17.839 41.91,19.096 42.418,19.096 40.894,20.353 41.402,20.353 41.91,20.353 42.418,20.353 40.894,21.611 41.402,21.611 41.91,21.611 42.418,21.611 40.894,22.868 41.402,22.868 41.91,22.868 42.418,22.868 41.91,24.126 42.418,24.126 41.402,25.383 41.91,25.383 42.418,25.383 50.558,27.692 40.894,32.18 41.402,32.18 41.91,32.18 42.418,32.18 40.894,33.438 41.402,33.438 41.91,33.438 42.418,33.438 40.894,34.695 41.402,34.695 41.91,34.695 42.418,34.695 40.894,35.952 41.402,35.952 41.91,35.952 42.418,35.952 41.91,37.21 42.418,37.21 40.894,38.467 41.402,38.467 41.91,38.467 42.418,38.467 40.894,39.725 41.402,39.725 41.91,39.725 42.418,39.725 40.894,40.85 41.402,40.85 41.91,40.85 42.418,40.85 40.894,42.108 41.402,42.108 41.91,42.108 42.418,42.108 41.91,43.365 42.418,43.365 40.894,44.623 41.402,44.623 41.91,44.623 42.418,44.623 67.31,44.948 66.802,45.511 67.31,45.511 40.894,45.88 41.402,45.88 41.91,45.88 42.418,45.88 66.294,46.097 66.802,46.097 67.31,46.097 65.786,46.646 66.294,46.645 66.802,46.645 67.31,46.645 40.894,47.137 41.402,47.137 41.91,47.137 42.418,47.137 65.278,47.214 65.786,47.203 66.294,47.203 66.802,47.203 67.31,47.203 41.91,48.395 42.418,48.395
  other v2: 55.358,9.269 55.866,9.269 56.374,9.269 56.882,9.269 55.358,10.526 55.866,10.526 56.374,10.526 56.882,10.526 55.358,11.784 55.866,11.784 56.374,11.784 56.882,11.784 55.358,13.041 55.866,13.041 56.374,13.041 56.882,13.041 55.358,14.299 55.866,14.299 56.374,14.299 56.882,14.299 55.358,15.556 55.866,15.556 56.374,15.556 56.882,15.556 55.358,16.813 55.866,16.813 56.374,16.813 56.882,16.813 55.358,18.071 55.866,18.071 56.374,18.071 56.882,18.071 55.358,19.196 55.866,19.196 56.374,19.196 56.882,19.196 55.358,20.454 55.866,20.454 56.374,20.454 56.882,20.454 55.358,21.711 55.866,21.711 56.374,21.711 56.882,21.711 55.358,22.969 55.866,22.969 56.374,22.969 56.882,22.969 55.358,24.226 55.866,24.226 56.374,24.226 56.882,24.226 55.358,25.483 55.866,25.483 56.374,25.483 56.882,25.483 55.358,26.741 55.866,26.741 56.374,26.741 56.882,26.741 55.521,33.438 56.029,33.438 56.537,33.438 55.521,34.695 56.029,34.695 56.537,34.695 55.521,35.952 56.029,35.952 56.537,35.952 55.521,37.21 56.029,37.21 56.537,37.21 55.521,38.467 56.029,38.467 56.537,38.467 55.521,39.725 56.029,39.725 56.537,39.725 55.521,40.85 56.029,40.85 56.537,40.85 55.521,42.108 56.029,42.108 56.537,42.108 55.521,43.365 56.029,43.365 56.537,43.365 55.521,44.623 56.029,44.623 56.537,44.623 55.521,45.88 56.029,45.88 56.537,45.88 55.521,47.137 56.029,47.137 56.537,47.137 55.521,48.395 56.029,48.395 56.537,48.395
  other v3: 33.845,4.334 34.995,4.334 52.327,5.08 53.477,5.08 52.902,6.03 34.131,27.709 35.281,27.709 34.713,28.414 49.95,28.527 51.1,28.527
VDD: C1.1 C2.1 C17.1 C18.1 C41.1 C42.1 C51.1 R3.2 U1.3 U2.1 U2.6 U3.1 U3.6 U4.1 U4.6 U10.1 U10.6 | length 116.6
  Top Layer w0.2: U4.6@54.302,4.08 54.322,4.06 U4.6@54.537,4.06
  Top Layer w0.25: v1@51.088,6.085 U4.1@51.327,6.085
  Top Layer w0.254: U3.1@33.02,5.334 33.015,5.339 33.015,5.837 v1(33.01,5.842) 33.01,6.832 C41.1@33.249,7.072 ; C17.1@33.249,30.516 33.476,30.289 v1(33.476,29.323) 33.476,29.254 33.389,29.168 33.389,28.716 33.382,28.709 U10.1@33.306,28.709 ; U3.6@35.82,3.334 35.831,3.334 35.838,3.327 35.838,2.898 v1(35.856,2.88) ; U10.6@36.106,26.709 v1@36.466,26.709 ; U2.1@49.216,29.534 v1@49.216,29.956 ; C18.1@49.26,30.82 49.333,30.747 v1(49.333,30.143) ; v1(50.928,6.175) 50.928,7.792 C42.1@51.111,7.975 ; U2.6@51.925,27.527 52.577,27.527 52.658,27.446 v1(52.727,27.446) ; U4.6@54.537,4.06 54.822,3.775 v1(54.874,3.775)
  Top Layer w0.5: v4(14.829,4.192) 14.829,2.906 C1.1@14.933,2.802 ; C1.1@15.156,2.737 C1.1@15.22,2.802
  Layer 1 w0.254: v1(33.476,29.323) 35.24,29.323 36.071,28.492 ; v1(36.66,26.584) 36.071,27.173 36.071,28.492 ; v1(50.928,6.175) 51.364,6.611 53.143,6.611 54.26,5.493 54.26,4.113 54.55,3.824 54.826,3.824 v1(54.874,3.775) ; v1(52.727,27.446) 51.681,28.492 51.681,29.143 50.68,30.143 v1(49.333,30.143) 47.683,28.492 36.071,28.492
  Layer 3 w0.254: v1(15.202,2.049) 15.575,2.423 35.219,2.423 v1@35.628,2.831
  Layer 4 w0.254: v1(33.01,5.842) 33.306,6.138 35.31,6.138 35.919,5.528 35.919,3.123 35.905,3.108 35.905,2.929 v1(35.856,2.88) 35.919,2.88 36.132,2.667 53.767,2.667 v1(54.874,3.775)
  Bottom Layer w0.254: v1(35.856,2.88) 36.313,2.423 37.951,2.423 38.1,2.572 38.1,25.969 37.486,26.584 v1(36.66,26.584)
  Bottom Layer w0.5: C51.1@15.202,1.2 v1(15.202,2.049) R3.2@15.202,2.899
  other v4: 14.329,4.192 15.329,4.192 14.329,5.192 14.829,5.192 15.329,5.192
VG_SR1_AH: R31.1 U10.4 | length 6
  Top Layer w0.254: R31.1@28.845,29.619 28.845,28.617 29.349,28.112 31.67,28.112 32.573,27.209 U10.4@33.306,27.209
VG_SR1_AL: R36.1 U10.10 | length 3.4
  Top Layer w0.254: U10.10@36.106,28.709 36.272,28.709 36.279,28.716 36.279,28.782 36.448,28.951 36.448,30.248 37.139,30.939 37.332,30.939 R36.1@37.68,31.287
VG_SR1_BH: R34.1 U2.4 | length 5.5
  Top Layer w0.254: R34.1@44.745,28.677 45.093,29.025 45.093,29.118 45.32,29.345 47.796,29.345 48.044,29.098 48.044,28.613 48.63,28.027 U2.4@49.125,28.027
VG_SR1_BL: R39.1 U2.10 | length 1.8
  Top Layer w0.254: U2.10@51.925,29.527 51.932,29.527 51.939,29.534 51.939,30.053 v1(51.946,30.059)
  Bottom Layer w0.254: v1(51.946,30.059) 52.855,30.059 R39.1@53.086,29.829
VG_SR2_AH: R58.1 U3.4 | length 5.6
  Top Layer w0.254: R58.1@29.111,6.368 29.111,5.313 30.16,4.264 31.924,4.264 32.131,4.056 32.131,4.042 32.339,3.834 U3.4@33.02,3.834
VG_SR2_AL: R62.1 U3.10 | length 3
  Top Layer w0.254: U3.10@35.82,5.334 35.986,5.334 35.993,5.341 35.993,5.507 36.614,6.128 36.614,6.429 R62.1@37.669,7.484
VG_SR2_BH: R59.1 U4.4 | length 6.4
  Top Layer w0.254: R59.1@47.747,8.059 48.044,7.762 48.044,5.678 48.353,5.369 50.116,5.369 50.905,4.58 U4.4@51.502,4.58
VG_SR2_BL: R63.1 U4.10 | length 3
  Top Layer w0.254: U4.10@54.302,6.08 54.324,6.08 54.331,6.087 54.331,7.138 55.044,7.851 R63.1@55.903,7.851
Vref: C55.2 C56.2 U5.1 U6.1 U20.1 U20.4 | length 35.6
  Top Layer w0.254: C55.2@60.227,28.025 60.252,28.025 60.6,28.373 60.6,28.495 60.627,28.522 v1(60.627,29.345) ; C56.2@61.379,5.084 C56.2@61.156,5.307 61.366,5.517 61.366,6.532 61.439,6.605 U6.1@61.576,6.605
  Top Layer w0.3: v1(60.627,29.345) 60.633,29.34 61.288,29.34 U5.1@61.293,29.334
  Top Layer w0.5: v1(61.379,4.573) C56.2@61.379,5.084
  Layer 1 w0.254: v1(60.627,29.345) 60.627,28.783 61.88,27.53 61.88,5.075 v1(61.379,4.573)
  Bottom Layer w0.254: v1(61.379,4.573) 61.448,4.573 61.553,4.679 U20.4@63.15,4.679 63.173,4.679 63.321,4.827 63.321,5.457 64.443,6.579 U20.1@65.7,6.579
